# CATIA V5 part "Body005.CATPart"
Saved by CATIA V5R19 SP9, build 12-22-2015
Part number: Body005
Definition: design
Nomenclature: Body005
Source: Unknown
Bounding box of the stored display mesh (mm): x 20.52 to 27.52, y 15.11 to 27.61, z 0 to 2
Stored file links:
  Z:\charly_robot\Body005.CATPart
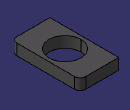
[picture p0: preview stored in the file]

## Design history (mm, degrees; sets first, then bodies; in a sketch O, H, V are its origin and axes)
AxisSystem1: origin (0, 0, 0), X (1, 0, 0), Y (0, 1, 0), Z (0, 0, 1)
Body1 "MANIFOLD_SOLID_BREP #36137" (main body)
  Solid1: solid without history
